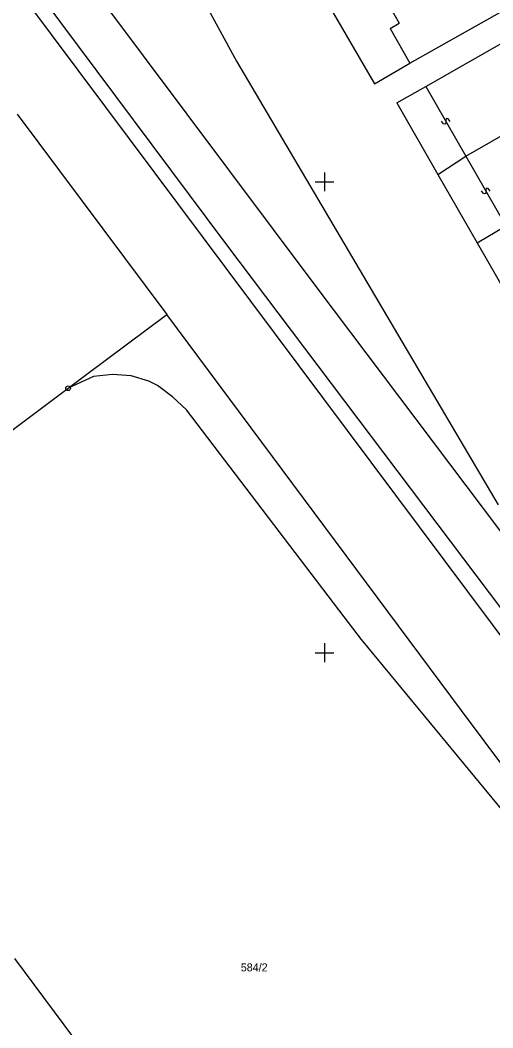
# Model space of a CAD drawing. Extents: x -493648 to -493033, y -1127718 to -1127026.
# Drawn here: x -493182.3 to -493132.1, y -1127439.8 to -1127332.8 of the extents above; entities that cross this region are included whole.
import ezdxf

# ---------------------------------------------------------------- set-up
doc = ezdxf.new("R2010")
doc.units = 0
doc.layers.add('katastrální mapa', color=7, linetype='Continuous')
doc.layers.add('síť', color=7, linetype='Continuous')

msp = doc.modelspace()

# ---------------------------------------------------------------- linework, layer by layer
at = {"layer": 'katastrální mapa'}
for p, q in [((-493183.29, -1127293.12), (-493159.33, -1127337.18)), ((-493198.67, -1127297.24), (-493150.83, -1127361.25)), ((-493202.36, -1127300.42), (-493160.5, -1127356.56)), ((-493202.62, -1127302.64), (-493173.25, -1127342.08)), ((-493144.45, -1127328.97), (-493142.07, -1127333.15)), ((-493140.96, -1127337.4), (-493127.89, -1127330.01)), ((-493149.33, -1127331.64), (-493144.69, -1127339.59)), ((-493143.04, -1127333.7), (-493142.07, -1127333.15)), ((-493139.25, -1127339.87), (-493127.12, -1127332.93)), ((-493143.04, -1127333.7), (-493140.96, -1127337.4)), ((-493159.33, -1127337.18), (-493131.56, -1127384.31)), ((-493144.69, -1127339.59), (-493140.96, -1127337.4)), ((-493142.31, -1127341.62), (-493139.25, -1127339.87)), ((-493139.25, -1127339.87), (-493135.01, -1127347.27)), ((-493135.01, -1127347.27), (-493122.88, -1127340.31)), ((-493142.31, -1127341.62), (-493137.96, -1127349.22)), ((-493182.62, -1127342.8), (-493166.74, -1127364.1)), ((-493173.25, -1127342.08), (-493126.36, -1127404.86)), ((-493137.38, -1127343.83), (-493137.6, -1127343.55)), ((-493137.25, -1127343.87), (-493137.38, -1127343.83)), ((-493137.16, -1127343.82), (-493137.25, -1127343.87)), ((-493137.12, -1127343.68), (-493137.16, -1127343.82)), ((-493137.1, -1127343.32), (-493137.14, -1127343.46)), ((-493137.14, -1127343.46), (-493137.12, -1127343.68)), ((-493137.01, -1127343.27), (-493137.1, -1127343.32)), ((-493136.88, -1127343.31), (-493137.01, -1127343.27)), ((-493136.66, -1127343.59), (-493136.88, -1127343.31)), ((-493137.96, -1127349.22), (-493135.01, -1127347.27)), ((-493135.01, -1127347.27), (-493130.75, -1127354.68)), ((-493137.96, -1127349.22), (-493133.81, -1127356.48)), ((-493133.13, -1127351.24), (-493133.35, -1127350.96)), ((-493133, -1127351.27), (-493133.13, -1127351.24)), ((-493132.91, -1127351.22), (-493133, -1127351.27)), ((-493132.87, -1127351.09), (-493132.91, -1127351.22)), ((-493132.85, -1127350.73), (-493132.89, -1127350.86)), ((-493132.89, -1127350.86), (-493132.87, -1127351.09)), ((-493132.76, -1127350.68), (-493132.85, -1127350.73)), ((-493132.63, -1127350.71), (-493132.76, -1127350.68)), ((-493132.41, -1127350.99), (-493132.63, -1127350.71)), ((-493133.81, -1127356.48), (-493130.75, -1127354.68)), ((-493160.5, -1127356.56), (-493118.62, -1127412.12)), ((-493133.81, -1127356.48), (-493129.51, -1127363.99)), ((-493150.83, -1127361.25), (-493125.99, -1127394.24)), ((-493175.22, -1127370.43), (-493166.74, -1127364.1)), ((-493177.2, -1127371.91), (-493175.22, -1127370.43)), ((-493174.51, -1127370.65), (-493177.2, -1127371.91)), ((-493254.36, -1127429.53), (-493177.2, -1127371.91)), ((-493182.89, -1127432.48), (-493156.39, -1127468.02))]:
    msp.add_line(p, q, dxfattribs=at)
for points in [[(-493085.93, -1127472.5), (-493135.46, -1127406.14), (-493166.74, -1127364.1)], [(-493085.93, -1127472.5), (-493087.58, -1127473.97), (-493099.04, -1127458.64), (-493107.51, -1127451.54), (-493108.83, -1127450.05), (-493116, -1127440.29), (-493118.72, -1127435.67), (-493126.88, -1127421.87), (-493146.06, -1127398.58), (-493147.9, -1127396.18), (-493164.64, -1127374.21), (-493166.11, -1127372.81), (-493167.7, -1127371.62), (-493168.62, -1127371.17), (-493170.51, -1127370.59), (-493172.5, -1127370.44), (-493174.51, -1127370.65)]]:
    msp.add_lwpolyline(points, dxfattribs=at)
for radius in [0.25, 0.005]:
    msp.add_circle((-493177.2, -1127371.91), radius, dxfattribs=at)
at = {"layer": 'síť'}
for p, q in [((-493150, -1127349), (-493150, -1127351)), ((-493151, -1127350), (-493149, -1127350)), ((-493150, -1127399), (-493150, -1127401)), ((-493151, -1127400), (-493149, -1127400))]:
    msp.add_line(p, q, dxfattribs=at)

# ---------------------------------------------------------------- texts
at = {"layer": 'katastrální mapa'}
msp.add_text('584/2', height=0.849996, dxfattribs=at).set_placement((-493158.88, -1127433.84))

doc.saveas('drawing.dxf')
